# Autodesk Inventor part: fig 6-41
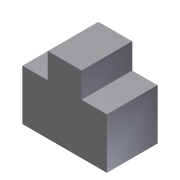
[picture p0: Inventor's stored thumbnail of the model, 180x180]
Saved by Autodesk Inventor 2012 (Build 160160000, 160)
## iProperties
Created: 2005-12
Part Number: fig 6-41
Document SubType Name: Modeling
Designer: CADCIM
Density: 1 g/cm^3
Material: Default
Author: CADCIM
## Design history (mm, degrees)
sketch "Sketch1"
  geometry: L1 (10, 15)-(25, 15); L2 (25, 15)-(25, -15); L3 (25, -15)-(-25, -15); L4 (-25, -15)-(-25, 15); L5 (-25, 15)-(-10, 15); L6 (10, 15)-(10, 30); L7 (10, 30)-(-10, 30); L8 (-10, 30)-(-10, 15)
  constraints: 16 end point, 3 parallel, 3 perpendicular, 2 equal length, 1 collinear, 1 horizontal
  dimensions: "d0" = 50 distance of L2.end L3.end; "d2" = 30 distance of L1.end L2.end; "d3" = 15 distance of L1.start L1.end; "d11" = 15 distance of L7.end L5.end
extrude "Extrusion1" new body sketch "Sketch1" stored distance "d7" = 30; taper "d8" = 0 deg
body "Solid1"
